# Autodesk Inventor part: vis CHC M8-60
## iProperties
Created: 2002-05
Part Number: vis CHC M8-60
Material: Par défaut
Catalog Web Link: www.traceparts.com
Description: Vis à métaux - Tête hexagonale - tige entièrement filetée DIN 933 - M8x60 - 8,8
Document SubType Name: Modélisation
Designer: REVEST Pierre
Control State: 0
Master: False
Checked Out: False
Shininess: 20.0
Length Units: 11269
Angle Units: 11279
Time Units: 11290
Mass Units: 11283
Length Display Precision: 3
Angle Display Precision: 2
Density: 0.0
Volumn: 0.0
Area: 0.0
PropertySet Name: Model Information
Author: REVEST Pierre
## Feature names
1. Base1
